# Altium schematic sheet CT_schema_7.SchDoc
size 277 x 170 mm
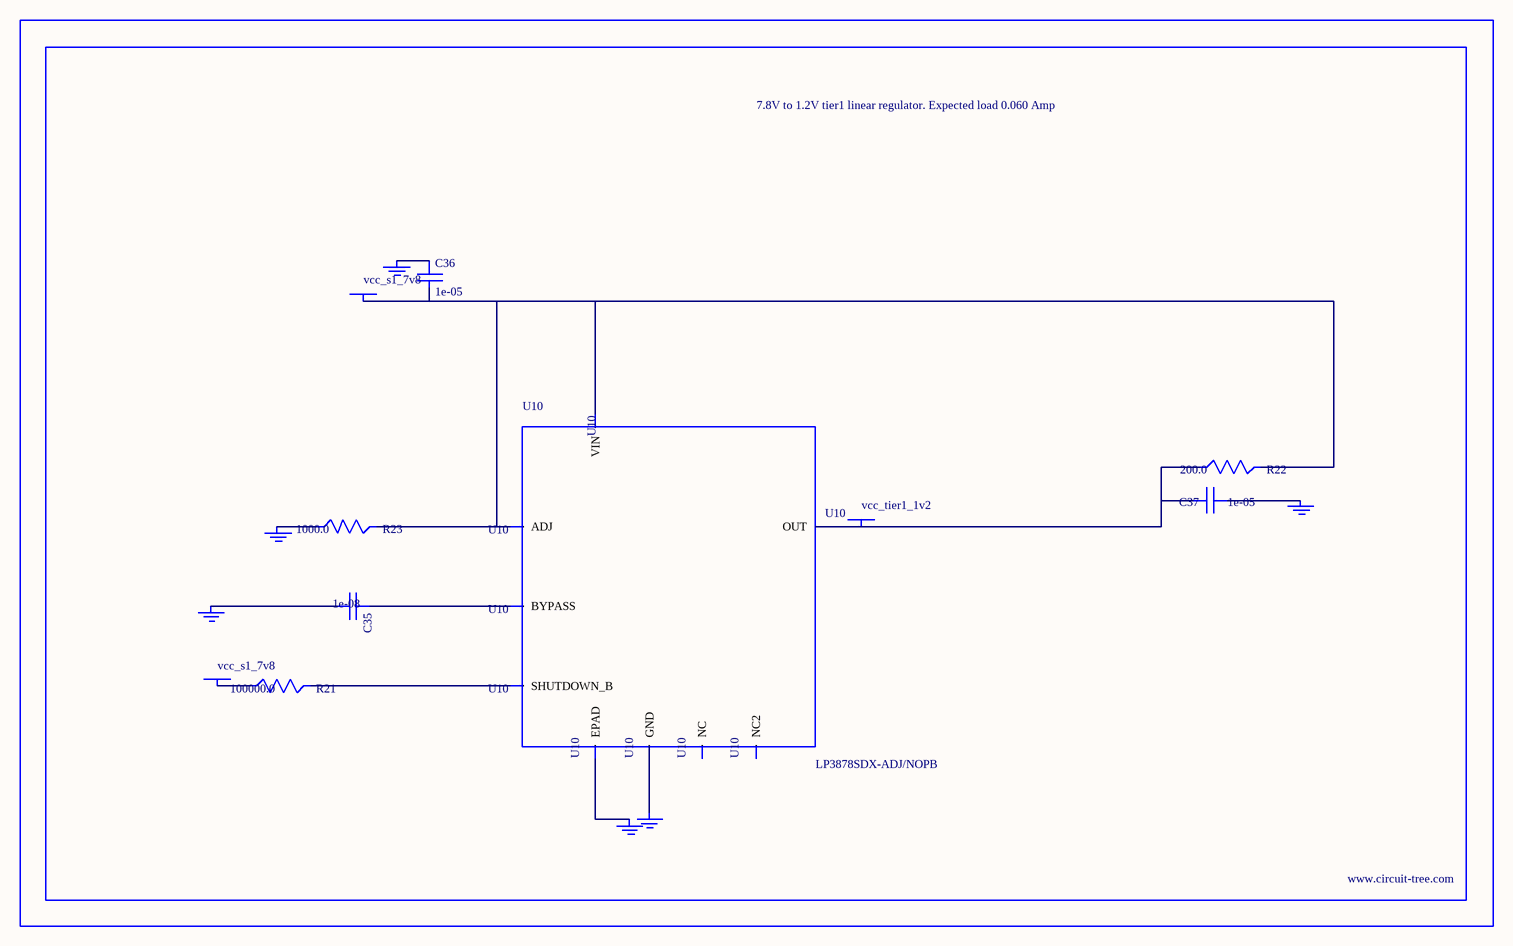
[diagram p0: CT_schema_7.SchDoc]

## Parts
BORDER6  (no value)
C35  1e-08  [C0402]
C36  1e-05  [C1206]
C37  1e-05  [C0805]
GND_INSTANCE_6_0  (no value)
GND_INSTANCE_6_1  (no value)
GND_INSTANCE_6_2  (no value)
GND_INSTANCE_6_3  (no value)
GND_INSTANCE_6_4  (no value)
GND_INSTANCE_6_5  (no value)
POWER_INSTANCE_6_0  vcc_s1_7v8
POWER_INSTANCE_6_1  vcc_s1_7v8
POWER_INSTANCE_6_2  vcc_tier1_1v2
R21  100000.0  [R0603]
R22  200.0  [R0603]
R23  1000.0  [R0603]
U10  LP3878SDX-ADJ/NOPB  [WSON-8]

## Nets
NetC35_1: C35.1 U10.1(BYPASS)
NetC35_2: C35.2 GND_INSTANCE_6_0.0(GND)
NetC36_1: C36.1 GND_INSTANCE_6_1.0(GND)
NetC36_2: C36.2 POWER_INSTANCE_6_0.0(PWR) R22.2 R23.2 U10.4(VIN) U10.6(ADJ)
NetC37_1: C37.1 GND_INSTANCE_6_2.0(GND)
NetC37_2: C37.2 POWER_INSTANCE_6_2.0(PWR) R22.1 U10.5(OUT)
NetGND_INSTANCE_6_3_0: GND_INSTANCE_6_3.0(GND) R23.1
NetGND_INSTANCE_6_4_0: GND_INSTANCE_6_4.0(GND) U10.PAD(EPAD)
NetGND_INSTANCE_6_5_0: GND_INSTANCE_6_5.0(GND) U10.3(GND)
NetPOWER_INSTANCE_6_1_0: POWER_INSTANCE_6_1.0(PWR) R21.1
NetR21_2: R21.2 U10.8(SHUTDOWN_B)

Not connected (* = marked no-connect by the designer): U10 2(NC) 7(NC2)

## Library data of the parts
BORDER6 = BORDER_PAGE6
C35 = C0402C103K3RAC
C36 = C1206C106K3RACTU
C37 = GRM219R60J106ME19D
GND_INSTANCE_6_0-GND_INSTANCE_6_5 = GND
POWER_INSTANCE_6_0-POWER_INSTANCE_6_2 = PWR
R21 = RC0603JR-07100KL
R22 = RC0603JR-07200RL
R23 = RC0603JR-071KL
